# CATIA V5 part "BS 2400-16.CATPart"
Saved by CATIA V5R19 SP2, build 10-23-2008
Part number: BS 2400-16
Bounding box of the stored display mesh (mm): x -37.351 to 37.351, y -37.351 to 37.351, z 0 to 77
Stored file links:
  C:\Users\Bora\Desktop\3D Katı model\BS serisi\BS 2400\BS 2400-16.CATPart
  C:\Program Files\Dassault Systemes\B19\intel_a\reffiles\standard\MetricThickPitch.txt
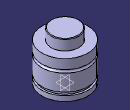
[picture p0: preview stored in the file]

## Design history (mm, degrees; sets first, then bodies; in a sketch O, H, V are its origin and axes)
Body1 (main body)
  Sketch1 on yz-plane, origin (0, 0, 0), H (0, 1, 0), V (0, 0, 1)
    point P1 (22.5, 76)
    point P3 (22.5, 76)
    point P7 (37.5, 44.5)
    point P9 (37.5, 44.5)
    point P10 (37.5, 39.5)
    point P14 (37.5, 39.5)
    line L1 (22.5, 76) -> (22.5, 60)
    arc A1 centre (21.5, 76) radius 1 from (22.5, 76) to (21.5, 77) ccw
    line L2 (37.5, 0) -> (37.5, 8)
    line L3 (37.5, 44.5) -> (37.5, 60)
    arc A2 centre (37.5, 42) radius 2.5 from (37.5, 44.5) to (37.5, 39.5) ccw
    line L4 (34.5, 13) -> (34.5, 8)
    line L5 (37.5, 13) -> (37.5, 39.5)
    line L6 (21.5, 77) -> (0, 77)
    point P15 (0, 77)
    line L7 (22.5, 60) -> (37.5, 60)
    line L8 (0, 0) -> (37.5, 0)
    line L9 (34.5, 13) -> (37.5, 13)
    line L10 (34.5, 8) -> (37.5, 8)
    coincidence: P15 V, P1 P3, P7 P9, P10 P14
    tangency: L6 A1
    horizontal: L7 H, L8 H, L9 H, L10 H
  Shaft1: profile Sketch1, axis Sketch1.V, angle 360
  Sketch2 on face of Shaft1 from Sketch1.L8, origin (0, 0, 0), H (1, 0, 0), V (0, -1, 0)
    point P1 (20, 0)
    distance P1 V = 20
  Hole1: placed by Sketch2, at (20, 0, 0) direction (0, 0, 1), diameter 6.647, depth 5, threaded "M8", thread diameter 8, thread depth 5, pitch 1.25
  CircPattern1: of Hole1, instances 4, angular step 90, axis from xy-plane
